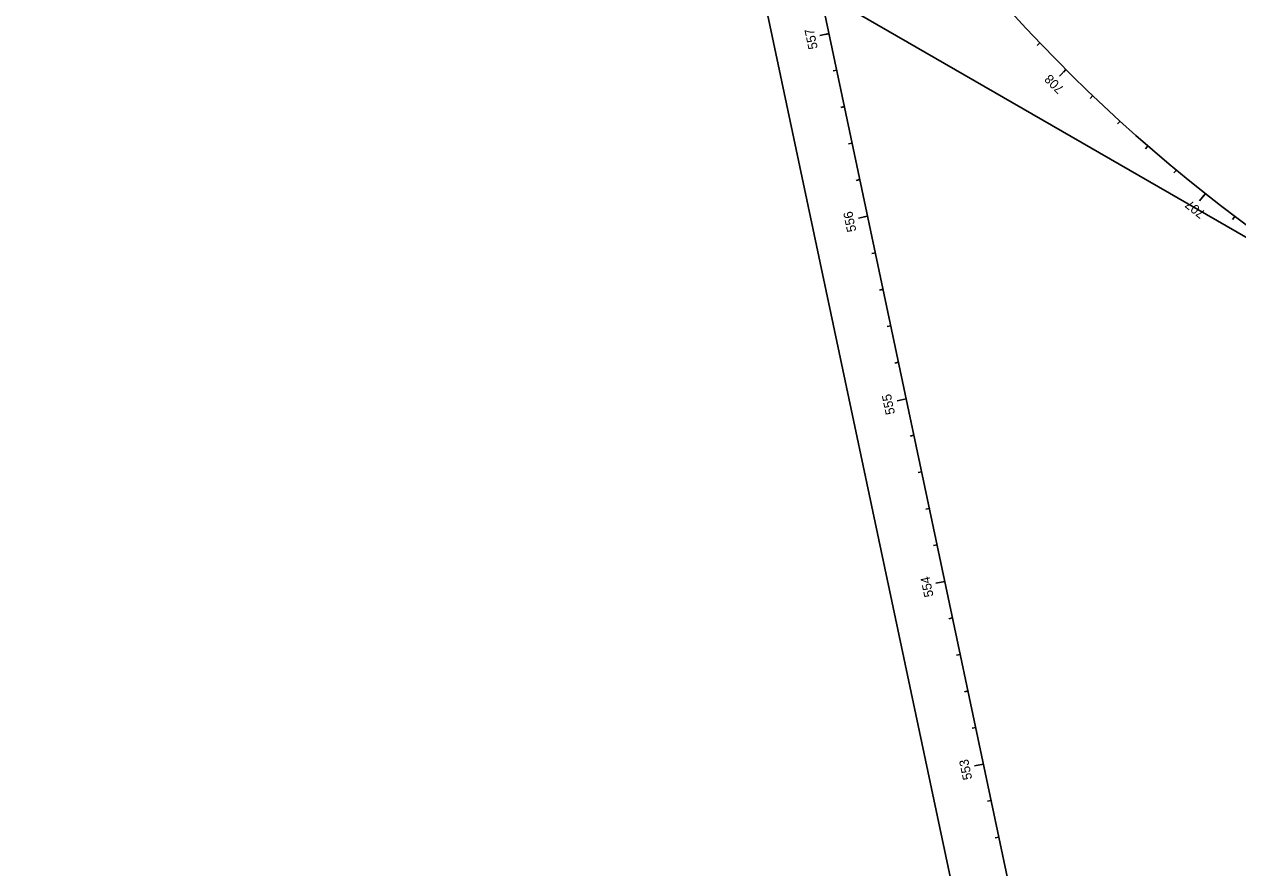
# Model space of a CAD drawing. Extents: x 2003883 to 2007688, y 399149 to 412300.
# Drawn here: x 2005600 to 2006250, y 402640 to 403092 of the extents above; entities that cross this region are included whole.
import ezdxf

# ---------------------------------------------------------------- set-up
doc = ezdxf.new("R2010")
doc.units = 0
for name, color, linetype in [('DataBoxWt2', 7, 'Continuous'), ('Default', 7, 'Continuous'), ('EaseLine_ep', 7, 'Continuous'), ('PropertyLine_ep', 7, 'Continuous'), ('PropertyLineHook_ep', 7, 'Continuous'), ('PropertyLineSymbol_ep', 7, 'Continuous'), ('SubDivLine', 7, 'Continuous'), ('SubDivLineText', 7, 'Continuous'), ('SubLotNumberText', 7, 'Continuous')]:
    doc.layers.add(name, color=color, linetype=linetype)

msp = doc.modelspace()

# ---------------------------------------------------------------- linework, layer by layer
at = {"layer": 'DataBoxWt2'}
for p, q in [((2006157.95, 403067.46), (2006156.54, 403066.04)), ((2006051.7, 402988.92), (2006049.74, 402988.51)), ((2006093.07, 402793.25), (2006091.11, 402792.83))]:
    msp.add_line(p, q, dxfattribs=at)
at = {"layer": 'Default'}
msp.add_line((2006223.92, 402174.38), (2005094.48, 407516.05), dxfattribs=at)
at = {"layer": 'EaseLine_ep'}
for p, q in [((2006194.57, 402168.18), (2005065.13, 407509.84)), ((2006833.64, 402642.95), (2005101.74, 403643.22))]:
    msp.add_line(p, q, dxfattribs=at)
msp.add_arc((2006780.04, 403691.29), 881, 190.93889, 239.99111, dxfattribs=at)
at = {"layer": 'PropertyLine_ep'}
msp.add_line((2006223.92, 402174.38), (2005094.48, 407516.05), dxfattribs=at)
at = {"layer": 'PropertyLineHook_ep'}
for p, q in [((2006031.01, 403086.76), (2006026.12, 403085.72)), ((2006143.95, 403081.74), (2006142.5, 403080.36)), ((2006035.15, 403067.19), (2006033.19, 403066.78)), ((2006157.95, 403067.46), (2006154.42, 403063.92)), ((2006039.29, 403047.62), (2006037.33, 403047.21)), ((2006172.27, 403053.5), (2006170.89, 403052.05)), ((2006186.9, 403039.87), (2006185.56, 403038.39)), ((2006043.42, 403028.05), (2006041.47, 403027.64)), ((2006201.84, 403026.57), (2006200.53, 403025.06)), ((2006047.56, 403008.49), (2006045.6, 403008.07)), ((2006217.08, 403013.62), (2006215.8, 403012.08)), ((2006232.61, 403001.01), (2006229.5, 402997.1)), ((2006051.7, 402988.92), (2006046.81, 402987.89)), ((2006248.42, 402988.77), (2006247.21, 402987.17)), ((2006055.84, 402969.35), (2006053.88, 402968.94)), ((2006059.97, 402949.79), (2006058.02, 402949.37)), ((2006064.11, 402930.22), (2006062.15, 402929.8)), ((2006068.25, 402910.65), (2006066.29, 402910.24)), ((2006072.38, 402891.08), (2006067.49, 402890.05)), ((2006076.52, 402871.52), (2006074.57, 402871.1)), ((2006080.66, 402851.95), (2006078.7, 402851.53)), ((2006084.8, 402832.38), (2006082.84, 402831.97)), ((2006088.93, 402812.81), (2006086.98, 402812.4)), ((2006093.07, 402793.25), (2006088.18, 402792.21)), ((2006097.21, 402773.68), (2006095.25, 402773.26)), ((2006101.35, 402754.11), (2006099.39, 402753.7)), ((2006105.48, 402734.54), (2006103.53, 402734.13)), ((2006109.62, 402714.98), (2006107.66, 402714.56)), ((2006113.76, 402695.41), (2006108.87, 402694.37)), ((2006117.9, 402675.84), (2006115.94, 402675.43)), ((2006122.03, 402656.27), (2006120.08, 402655.86))]:
    msp.add_line(p, q, dxfattribs=at)
at = {"layer": 'SubDivLine'}
msp.add_arc((2006780.04, 403691.29), 881, 190.93889, 239.99111, dxfattribs=at)
at = {"layer": 'SubDivLineText'}
for p, q in [((2006031.01, 403086.76), (2006029.05, 403086.34)), ((2006157.95, 403067.46), (2006156.54, 403066.04)), ((2006232.61, 403001.01), (2006231.37, 402999.45)), ((2006051.7, 402988.92), (2006049.74, 402988.51)), ((2006072.38, 402891.08), (2006067.49, 402890.05)), ((2006093.07, 402793.25), (2006091.11, 402792.83)), ((2006113.76, 402695.41), (2006111.8, 402695))]:
    msp.add_line(p, q, dxfattribs=at)

# ---------------------------------------------------------------- texts
at = {"layer": 'PropertyLineSymbol_ep'}
for s, rotation, p in [('557', 101.93882, (2006025.01, 403078.9)), ('708', 135.08022, (2006157.29, 403057.53)), ('707', 141.58372, (2006233, 402991.13)), ('556', 101.93882, (2006045.71, 402981)), ('555', 101.93882, (2006066.4, 402883.13)), ('554', 101.93882, (2006087.07, 402785.37)), ('553', 101.93882, (2006107.78, 402687.44))]:
    msp.add_text(s, height=4.98, rotation=rotation, dxfattribs=at).set_placement(p)
at = {"layer": 'SubLotNumberText'}
msp.add_text('555', height=4.98, rotation=101.93882, dxfattribs=at).set_placement((2006066.4, 402883.13))

doc.saveas('drawing.dxf')
